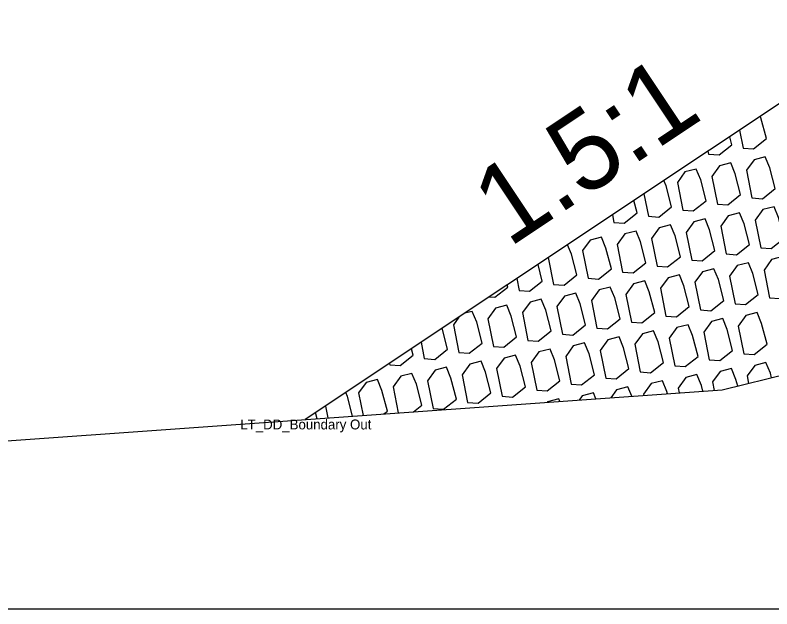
# Model space of a CAD drawing. Extents: x -26 to 203, y -10 to 20020.
# Drawn here: x 61.99 to 69.63, y 3000 to 3006 of the extents above; entities that cross this region are included whole.
import ezdxf

# ---------------------------------------------------------------- set-up
doc = ezdxf.new("R2010")
doc.units = 0
for name, color, linetype in [('Default', 7, 'Continuous'), ('Exist Cross Section Cell', 7, 'Continuous'), ('Exist XS Ground Line', 7, 'Continuous'), ('Old_Level_1', 7, 'Continuous'), ('Prop CMT Rip Rap Class II', 7, 'Continuous'), ('Prop XS Side Slope Text', 7, 'Continuous')]:
    doc.layers.add(name, color=color, linetype=linetype)

msp = doc.modelspace()

# ---------------------------------------------------------------- linework, layer by layer
at = {"layer": 'Exist Cross Section Cell'}
msp.add_line((0, 3000), (100, 3000), dxfattribs=at)
at = {"layer": 'Exist XS Ground Line'}
for p, q in [((69.1249, 3002.2125), (75.8737, 3003.8749)), ((57.0102, 3001.352), (69.1249, 3002.2125))]:
    msp.add_line(p, q, dxfattribs=at)
at = {"layer": 'Old_Level_1'}
for p, q in [((69.3016, 3004.8375), (69.3376, 3004.6561)), ((68.983, 3004.6251), (68.989, 3004.5946)), ((68.3358, 3004.1936), (68.3807, 3003.9676)), ((68.0172, 3003.9812), (68.0321, 3003.9061)), ((67.37, 3003.5498), (67.4238, 3003.2791)), ((67.0514, 3003.3374), (67.0752, 3003.2177)), ((66.0857, 3002.6935), (66.1183, 3002.5292)), ((65.767, 3002.4811), (65.7697, 3002.4677)), ((65.1199, 3002.0496), (65.1437, 3001.9297)), ((65.0354, 3001.922), (65.0197, 3001.9828))]:
    msp.add_line(p, q, dxfattribs=at)
for points in [[(69.3376, 3004.6561), (69.4429, 3004.6484), (69.5724, 3004.7516), (69.518, 3004.9622), (69.5116, 3004.9776)], [(68.989, 3004.5946), (69.0943, 3004.587), (69.2238, 3004.6902), (69.2027, 3004.7716)], [(68.3807, 3003.9676), (68.486, 3003.9599), (68.6155, 3004.0632), (68.5611, 3004.2737), (68.5384, 3004.3287)], [(68.0321, 3003.9061), (68.1374, 3003.8985), (68.2669, 3004.0017), (68.2347, 3004.1262)], [(67.4238, 3003.2791), (67.5291, 3003.2715), (67.6586, 3003.3747), (67.6041, 3003.5853), (67.5652, 3003.6799)], [(67.0752, 3003.2177), (67.1805, 3003.21), (67.31, 3003.3132), (67.2667, 3003.4809)], [(66.7745, 3003.1527), (66.8319, 3003.1485), (66.9614, 3003.2518), (66.9558, 3003.2736)], [(66.4672, 3002.9478), (66.4113, 3002.8706), (66.4669, 3002.5907)], [(66.4669, 3002.5907), (66.5721, 3002.583), (66.7017, 3002.6862), (66.6472, 3002.8968), (66.6021, 3003.0065), (66.5254, 3002.9867)], [(66.1183, 3002.5292), (66.2235, 3002.5215), (66.3531, 3002.6248), (66.2986, 3002.8353), (66.2986, 3002.8354)], [(65.7697, 3002.4677), (65.875, 3002.4601), (66.0045, 3002.5633), (65.9877, 3002.6282)], [(69.6253, 3002.3358), (69.6138, 3002.3804), (69.5686, 3002.4901), (69.4549, 3002.4607), (69.3778, 3002.3542), (69.3929, 3002.2785)], [(69.2826, 3002.2514), (69.2652, 3002.3189), (69.22, 3002.4286), (69.1063, 3002.3992), (69.0292, 3002.2928), (69.0463, 3002.2069)], [(66.0079, 3001.9911), (66.0934, 3002.0592), (66.0389, 3002.2698), (65.9938, 3002.3795), (65.88, 3002.3501), (65.803, 3002.2436), (65.8553, 3001.9803)], [(68.9318, 3002.1988), (68.9166, 3002.2575), (68.8714, 3002.3672), (68.7577, 3002.3377), (68.6806, 3002.2313), (68.6905, 3002.1816)], [(65.7099, 3001.9699), (65.7448, 3001.9978), (65.6903, 3002.2083), (65.6452, 3002.318), (65.5314, 3002.2886), (65.4544, 3002.1822), (65.4995, 3001.955)], [(68.5738, 3002.1734), (68.568, 3002.196), (68.5228, 3002.3057), (68.4091, 3002.2763), (68.332, 3002.1698), (68.3347, 3002.1564)], [(65.3933, 3001.9475), (65.3417, 3002.1469), (65.3254, 3002.1866)], [(67.8507, 3002.122), (67.8256, 3002.1828), (67.7119, 3002.1533), (67.6804, 3002.1099)], [(68.2139, 3002.1478), (68.1742, 3002.2442), (68.0605, 3002.2148), (68.001, 3002.1327)], [(67.4874, 3002.0962), (67.477, 3002.1213), (67.3633, 3002.0919), (67.3599, 3002.0871)]]:
    msp.add_lwpolyline(points, dxfattribs=at)
for points in [[(69.4265, 3004.152), (69.5318, 3004.1444), (69.6613, 3004.2476), (69.6068, 3004.4581), (69.5617, 3004.5678), (69.4479, 3004.5384), (69.3709, 3004.432)], [(69.0779, 3004.0905), (69.1832, 3004.0829), (69.3127, 3004.1861), (69.2583, 3004.3967), (69.2131, 3004.5064), (69.0993, 3004.4769), (69.0223, 3004.3705)], [(68.7293, 3004.0291), (68.8346, 3004.0214), (68.9641, 3004.1246), (68.9097, 3004.3352), (68.8645, 3004.4449), (68.7507, 3004.4155), (68.6737, 3004.3091)], [(69.5154, 3003.6479), (69.6206, 3003.6403), (69.7502, 3003.7435), (69.6957, 3003.9541), (69.6506, 3004.0638), (69.5368, 3004.0343), (69.4598, 3003.9279)], [(68.8182, 3003.525), (68.9234, 3003.5173), (69.053, 3003.6206), (68.9985, 3003.8311), (68.9534, 3003.9408), (68.8396, 3003.9114), (68.7626, 3003.805)], [(69.1668, 3003.5865), (69.272, 3003.5788), (69.4016, 3003.682), (69.3471, 3003.8926), (69.302, 3004.0023), (69.1882, 3003.9729), (69.1112, 3003.8665)], [(68.4696, 3003.4635), (68.5748, 3003.4559), (68.7044, 3003.5591), (68.6499, 3003.7697), (68.6048, 3003.8794), (68.491, 3003.8499), (68.414, 3003.7435)], [(68.121, 3003.4021), (68.2262, 3003.3944), (68.3558, 3003.4976), (68.3013, 3003.7082), (68.2562, 3003.8179), (68.1424, 3003.7885), (68.0654, 3003.6821)], [(67.7724, 3003.3406), (67.8777, 3003.3329), (68.0072, 3003.4362), (67.9527, 3003.6467), (67.9076, 3003.7564), (67.7938, 3003.727), (67.7168, 3003.6206)], [(69.6043, 3003.1439), (69.7095, 3003.1362), (69.8391, 3003.2394), (69.7846, 3003.45), (69.7395, 3003.5597), (69.6257, 3003.5303), (69.5486, 3003.4239)], [(69.2557, 3003.0824), (69.3609, 3003.0747), (69.4905, 3003.178), (69.436, 3003.3885), (69.3909, 3003.4982), (69.2771, 3003.4688), (69.2, 3003.3624)], [(68.9071, 3003.0209), (69.0123, 3003.0133), (69.1419, 3003.1165), (69.0874, 3003.3271), (69.0423, 3003.4368), (68.9285, 3003.4073), (68.8514, 3003.3009)], [(68.5585, 3002.9595), (68.6637, 3002.9518), (68.7933, 3003.055), (68.7388, 3003.2656), (68.6937, 3003.3753), (68.5799, 3003.3459), (68.5029, 3003.2394)], [(67.8613, 3002.8365), (67.9665, 3002.8289), (68.0961, 3002.9321), (68.0416, 3003.1427), (67.9965, 3003.2524), (67.8827, 3003.2229), (67.8057, 3003.1165)], [(68.2099, 3002.898), (68.3151, 3002.8903), (68.4447, 3002.9936), (68.3902, 3003.2041), (68.3451, 3003.3138), (68.2313, 3003.2844), (68.1543, 3003.178)], [(67.5127, 3002.7751), (67.6179, 3002.7674), (67.7475, 3002.8706), (67.693, 3003.0812), (67.6479, 3003.1909), (67.5341, 3003.1615), (67.4571, 3003.055)], [(67.1641, 3002.7136), (67.2693, 3002.7059), (67.3989, 3002.8092), (67.3444, 3003.0197), (67.2993, 3003.1294), (67.1855, 3003.1), (67.1085, 3002.9936)], [(66.8155, 3002.6521), (66.9207, 3002.6445), (67.0503, 3002.7477), (66.9958, 3002.9583), (66.9507, 3003.068), (66.8369, 3003.0385), (66.7599, 3002.9321)], [(69.3445, 3002.5783), (69.4498, 3002.5707), (69.5793, 3002.6739), (69.5249, 3002.8845), (69.4797, 3002.9942), (69.366, 3002.9647), (69.2889, 3002.8583)], [(68.6473, 3002.4554), (68.7526, 3002.4477), (68.8821, 3002.551), (68.8277, 3002.7615), (68.7826, 3002.8712), (68.6688, 3002.8418), (68.5917, 3002.7354)], [(68.9959, 3002.5169), (69.1012, 3002.5092), (69.2307, 3002.6124), (69.1763, 3002.823), (69.1312, 3002.9327), (69.0174, 3002.9033), (68.9403, 3002.7968)], [(68.2987, 3002.3939), (68.404, 3002.3863), (68.5335, 3002.4895), (68.4791, 3002.7001), (68.434, 3002.8098), (68.3202, 3002.7803), (68.2431, 3002.6739)], [(67.9501, 3002.3325), (68.0554, 3002.3248), (68.185, 3002.428), (68.1305, 3002.6386), (68.0854, 3002.7483), (67.9716, 3002.7189), (67.8945, 3002.6124)], [(67.6016, 3002.271), (67.7068, 3002.2633), (67.8364, 3002.3666), (67.7819, 3002.5771), (67.7368, 3002.6868), (67.623, 3002.6574), (67.5459, 3002.551)], [(67.253, 3002.2095), (67.3582, 3002.2019), (67.4878, 3002.3051), (67.4333, 3002.5157), (67.3882, 3002.6254), (67.2744, 3002.5959), (67.1973, 3002.4895)], [(66.5558, 3002.0866), (66.661, 3002.0789), (66.7906, 3002.1822), (66.7361, 3002.3927), (66.691, 3002.5024), (66.5772, 3002.473), (66.5002, 3002.3666)], [(66.9044, 3002.1481), (67.0096, 3002.1404), (67.1392, 3002.2436), (67.0847, 3002.4542), (67.0396, 3002.5639), (66.9258, 3002.5345), (66.8488, 3002.428)], [(66.2072, 3002.0251), (66.3124, 3002.0175), (66.442, 3002.1207), (66.3875, 3002.3313), (66.3424, 3002.441), (66.2286, 3002.4115), (66.1516, 3002.3051)]]:
    msp.add_lwpolyline(points, close=True, dxfattribs=at)
at = {"layer": 'Prop CMT Rip Rap Class II'}
msp.add_lwpolyline([(80.1375, 3006), (71.0452, 3006), (64.9158, 3001.9135)], dxfattribs=at)

# ---------------------------------------------------------------- texts
at = {"layer": 'Default'}
msp.add_text('LT_DD_Boundary Out', height=0.1, dxfattribs=at).set_placement((64.2604, 3001.8135))
at = {"layer": 'Prop XS Side Slope Text'}
msp.add_text('1.5:1', height=0.8, rotation=33.69139, dxfattribs=at).set_placement((66.9714, 3003.6445))

doc.saveas('drawing.dxf')
